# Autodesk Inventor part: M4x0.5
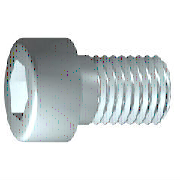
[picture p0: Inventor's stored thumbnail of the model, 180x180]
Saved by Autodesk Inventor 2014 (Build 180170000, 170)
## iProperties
IsCustomPart: 1
Company: 한국ATC센터
Created: 2014-10
Part Number: M4x0.5
Material: 강, 연강
Description: 6각머리 태핑 나사
Document SubType Name: Modeling
Standard: KS B 1003
Designer: 한국ATC센터
Standards Organization: KS
Language: ko-KR
Size Designation: M 4 x 16
Categories: <MemberInstance><Categories><Category DisplayName="조임쇠" InternalName="e4da775c-781d-43d5-af7c-5136215cf5a6" Mnemonic="FSTN"><Category DisplayName="볼트" InternalN
Density: 7.86 g/cm^3
Mass: 2.62973 g
Surface Area: 3.81119 cm^2
Volume: 0.334572 cm^3
Appearance: 강철
Author: KYOUNG IL JANG
Revision Number: 1
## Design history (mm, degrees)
sketch "스케치1"
  geometry: L1 (-1, 0)-(16, 0); L2 (16, 0)-(16, 2); L3 (16, 2)-(1.75, 2); L4 (1.75, 2)-(1.32, 2); L5 (1.32, 2)-(0, 2); L6 (0, 2)-(0, 3.5); L7 (0, 3.5)-(-4, 3.5); L8 (-4, 3.5)-(-4, 1.732); L9 (-4, 1.732)-(-2, 1.732); L10 (-2, 1.732)-(-1, 0); L11 (-8, 0)-(20, 0) reference; L12 (0, -0.7)-(0, 4.2) reference; L13 (1.75, 2)-(0, 2)
  constraints: 22 end point, 6 parallel, 2 collinear, 2 perpendicular, 1 horizontal, 1 point on line
  dimensions: "d1" = 14.25 distance from line of L3.end L2 (= GEL); "d2" = 0.42952 distance of L4.end L3.end (computed from GAL); "d3" = 4 distance between parallel lines of L8 L6 (= KOH); "d4" = 2 distance of L8.end L9.end (= INTI); "d5" = 60 deg angle of L10 L1; "d6" = 4 diameter of L3 L1 (= GD); "d7" = 4 diameter of L5 L1 (= BDM); "d8" = 3.4641 diameter of L9 L1 (= 1.1547 x SW); "d9" = 7 diameter of L7 L1 (= KOD); "d26" = 16 distance between parallel lines of L12 L2 (= NLG)
revolve "본체" sketch "스케치1" stored, may be unused: angle "d10" = 90 deg
sketch "스케치2"
  geometry: L1 (0, -4.9)-(0, 4.9) reference; L2 (-4.9, 0)-(4.9, 0) reference; L3 (1.732, 0)-(0.866, -1.5); L4 (0.866, -1.5)-(-0.866, -1.5); L5 (-0.866, -1.5)-(-1.732, 0); L6 (-1.732, 0)-(-0.866, 1.5); L7 (-0.866, 1.5)-(0.866, 1.5); L8 (0.866, 1.5)-(1.732, 0); 2 further points
  constraints: 12 end point, 1 coincident, 1 horizontal alignment, 1 point on line, 12 other
extrude "슬롯" join sketch "스케치2" stored distance "d11" = 10; taper "d12" = 0 deg
workplane "Work Plane1"
fillet "Fillet2" dims "d30" = 0.1 (= R)
body "Solid1"
fillet "모깎기1" dims "d17" = 0.4 (= RR)
feature "스레드" dims "d13" = 14.25 (= GEL), "d14" = 0
chamfer "모따기1" distance "d15" = 0.42941 (= -0.5 x SPD + 0.5 x GD); stored, may be unused: second distance "d16" = 0.42941 (= GUL), angle "d27" = 45 deg
other parameters: "GD" = 4 (= NND) [user parameter; used in 2 equation terms], "NLG" = 16 [user parameter; used in 1 equation term], "GEL" = 14.25 [user parameter; used in 2 equation terms], "KOD" = 7 [user parameter; used in 1 equation term], "KOH" = 4 [user parameter; used in 1 equation term], "INTI" = 2 [user parameter; used in 1 equation term], "GAL" = 0.42941 (= 0.61345 x PTC) [user parameter; used in 1 equation term], "GUL" = 0.42941 (= 0.61345 x PTC) [user parameter; used in 1 equation term], "BDM" = 4 (= NND) [user parameter; used in 1 equation term], "SW" = 3 [user parameter; used in 2 equation terms], "RR" = 0.4 [user parameter; used in 1 equation term], "SPD" = 3.14117 (= NND - 1.2269 x PTC) [user parameter; used in 1 equation term], "d19" = 0, "d28" = 0, "d29" = 0, "R" = 0.1 [user parameter; used in 1 equation term], "PHH" = 0.2 [user parameter], "GD1" = 3.14117 (= THREADDIA - 1.2269 x PTC) [user parameter], "THREADDIA" = 4 [user parameter; used in 1 equation term], "FAWI" = 45 deg [user parameter], "TPU" = 14.28571 (computed from PTC) [user parameter], "PTC" = 0.7 [user parameter; used in 5 equation terms], "NND" = 4 [user parameter; used in 3 equation terms], "TOA" = 30 deg [user parameter], "E0" = 3.465 (= 1.155 x SW) [user parameter]
